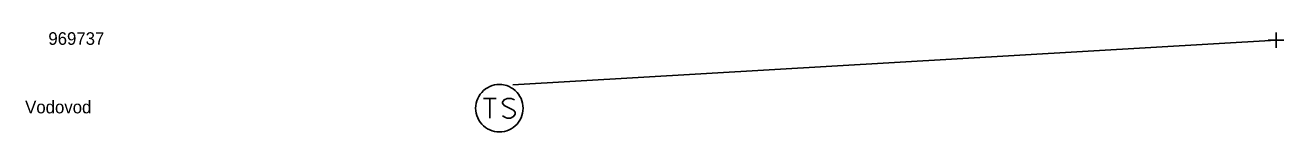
# Model space of a CAD drawing. Extents: x -788458 to -786145, y -1154772 to -1152372.
# Drawn here: x -787915.6 to -787815.2, y -1153491.6 to -1153483.7 of the extents above; entities that cross this region are included whole.
import ezdxf

# ---------------------------------------------------------------- set-up
doc = ezdxf.new("R2010")
doc.units = 0
for name, color, linetype in [('Vrstva 1', 7, 'Continuous'), ('Vrstva 25', 7, 'Continuous'), ('Vrstva 26', 7, 'Continuous'), ('Vrstva 27', 7, 'Continuous'), ('Vrstva 34', 7, 'Continuous'), ('Vrstva 59', 7, 'Continuous'), ('Vrstva 6', 7, 'Continuous')]:
    doc.layers.add(name, color=color, linetype=linetype)

# ---------------------------------------------------------------- blocks, each defined once
blk = doc.blocks.new('NN800')
at = {"layer": 'Vrstva 1'}
for points in [[(-0.44, 0.44), (0.44, -0.44)], [(-0.44, -0.44), (0.44, 0.44)]]:
    blk.add_lwpolyline(points, dxfattribs=at)
blk = doc.blocks.new('NN610')
at = {"layer": 'Vrstva 6'}
for points in [[(1.88, 0), (1.87, 0.2), (1.84, 0.39), (1.79, 0.58), (1.72, 0.77), (1.63, 0.94), (1.52, 1.11), (1.4, 1.26), (1.26, 1.4), (1.1, 1.53), (0.94, 1.63), (0.76, 1.72), (0.58, 1.8), (0.19, 1.88), (0.19, 1.88), (-0.01, 1.89), (-0.21, 1.88), (-0.4, 1.85), (-0.59, 1.8), (-0.78, 1.72), (-0.95, 1.63), (-1.12, 1.53), (-1.27, 1.4), (-1.41, 1.26), (-1.54, 1.11), (-1.64, 0.94), (-1.73, 0.77), (-1.8, 0.58), (-1.86, 0.39), (-1.89, 0.2), (-1.9, 0), (-1.89, -0.2), (-1.86, -0.39), (-1.8, -0.58), (-1.73, -0.77), (-1.64, -0.95), (-1.54, -1.11), (-1.41, -1.27), (-1.27, -1.41), (-1.12, -1.53), (-0.95, -1.64), (-0.78, -1.73), (-0.59, -1.8), (-0.4, -1.85), (-0.21, -1.88), (-0.01, -1.89), (0.19, -1.88), (0.39, -1.85), (0.58, -1.8), (0.76, -1.73), (0.94, -1.64), (1.1, -1.53), (1.26, -1.41), (1.4, -1.27), (1.52, -1.11), (1.63, -0.95), (1.72, -0.77), (1.79, -0.58), (1.84, -0.39), (1.87, -0.2), (1.88, 0)], [(-1.27, 0.78), (-0.26, 0.78)], [(-0.76, 0.78), (-0.76, -0.79)], [(1.19, 0.66), (0.94, 0.78), (0.62, 0.78), (0.37, 0.66), (0.24, 0.47), (0.24, 0.4), (0.37, 0.22), (1.12, -0.16), (1.25, -0.32), (1.25, -0.48), (1.12, -0.67), (0.87, -0.79), (0.62, -0.79), (0.49, -0.73), (0.24, -0.6)]]:
    blk.add_lwpolyline(points, dxfattribs=at)

msp = doc.modelspace()

# ---------------------------------------------------------------- linework, layer by layer
at = {"layer": 'Vrstva 59'}
msp.add_lwpolyline([(-787876.69, -1153487.88), (-787815.86, -1153484.33)], dxfattribs=at)

# ---------------------------------------------------------------- block references
at = {"layer": 'Vrstva 25'}
msp.add_blockref('NN610', (-787877.76, -1153489.74), dxfattribs=at)
at = {"layer": 'Vrstva 34', "rotation": 44.99999995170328}
msp.add_blockref('NN800', (-787815.86, -1153484.33), dxfattribs=at)

# ---------------------------------------------------------------- texts
at = {"layer": 'Vrstva 26'}
msp.add_text('969737', height=1, dxfattribs=at).set_placement((-787913.72, -1153484.7))
at = {"layer": 'Vrstva 27'}
msp.add_text('Vodovod', height=1, dxfattribs=at).set_placement((-787915.57, -1153490.15))

doc.saveas('drawing.dxf')
